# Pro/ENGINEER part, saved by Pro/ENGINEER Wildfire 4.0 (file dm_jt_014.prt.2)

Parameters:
  METRIC = "NO"

Other parameters: PITCH, DRILL_POINT_ANGLE, DRILL_DEPTH, DRILL_DIAMETER, THREAD_DIAMETER, THREADS_PER_INCH, THREAD_DEPTH, THREAD_LENGTH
